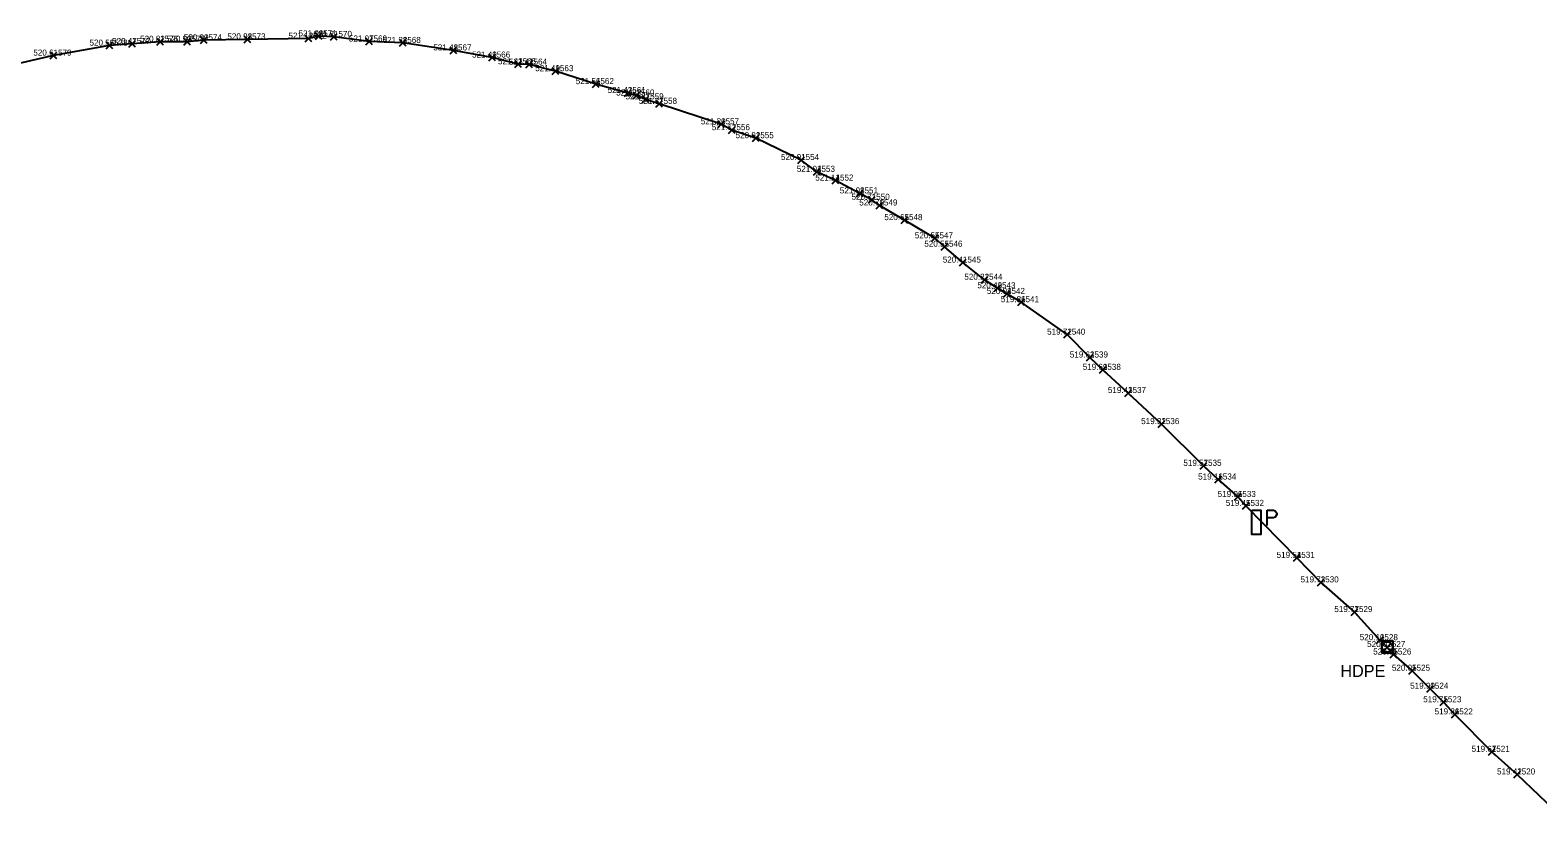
# Model space of a CAD drawing. Extents: x -874041 to -866452, y -1055592 to -1049889.
# Drawn here: x -873048.1 to -872799.1, y -1055397.3 to -1055267.6 of the extents above; entities that cross this region are included whole.
import ezdxf

# ---------------------------------------------------------------- set-up
doc = ezdxf.new("R2010")
doc.units = 0
for name, color, linetype in [('Vrstva 30', 7, 'Continuous'), ('Vrstva 32', 7, 'Continuous'), ('Vrstva 33', 7, 'Continuous'), ('Vrstva 60', 7, 'Continuous'), ('Vrstva 61', 7, 'Continuous')]:
    doc.layers.add(name, color=color, linetype=linetype)

msp = doc.modelspace()

# ---------------------------------------------------------------- linework, layer by layer
at = {"layer": 'Vrstva 30'}
msp.add_lwpolyline([(-872824.91, -1055370.41), (-872822.99, -1055370.41), (-872822.99, -1055368.49), (-872824.91, -1055368.49)], close=True, dxfattribs=at)
msp.add_circle((-872823.95, -1055369.45), 0.864, dxfattribs=at)
at = {"layer": 'Vrstva 32'}
for points in [[(-872851.86, -1055341.78), (-872854.3, -1055339.52), (-872861.27, -1055332.63), (-872866.77, -1055327.5), (-872870.93, -1055323.67), (-872873.06, -1055321.63), (-872876.81, -1055317.85), (-872884.45, -1055312.49), (-872886.77, -1055311.13), (-872888.33, -1055310.19), (-872890.48, -1055308.79), (-872894.05, -1055305.95), (-872897.09, -1055303.33), (-872898.66, -1055301.94), (-872903.7, -1055298.94), (-872907.84, -1055296.52), (-872909.11, -1055295.57), (-872911.05, -1055294.53), (-872915.1, -1055292.41), (-872918.16, -1055290.97), (-872920.77, -1055289.01), (-872928.26, -1055285.41), (-872932.2, -1055284.08), (-872934, -1055283.11), (-872944.24, -1055279.74), (-872946.45, -1055279), (-872947.98, -1055278.36), (-872949.4, -1055277.95), (-872954.67, -1055276.48), (-872961.36, -1055274.34), (-872965.71, -1055273.26), (-872967.52, -1055273.2), (-872971.8, -1055272.09), (-872978.19, -1055270.91), (-872986.57, -1055269.68), (-872992.14, -1055269.44), (-872997.94, -1055268.68), (-873000.46, -1055268.58), (-873002.13, -1055268.97), (-873012.21, -1055269.09), (-873019.41, -1055269.24), (-873022.21, -1055269.47), (-873026.63, -1055269.49), (-873031.25, -1055269.85), (-873034.99, -1055270.12), (-873044.26, -1055271.77), (-873051.62, -1055273.48)], [(-872851.86, -1055341.78), (-872848.64, -1055344.66), (-872847.29, -1055346.14), (-872838.9, -1055354.72), (-872834.95, -1055358.77), (-872829.37, -1055363.67), (-872825.17, -1055368.31), (-872823.95, -1055369.45), (-872822.94, -1055370.68), (-872819.86, -1055373.36), (-872816.84, -1055376.33), (-872814.68, -1055378.56), (-872812.8, -1055380.57), (-872806.69, -1055386.75), (-872802.49, -1055390.49), (-872795.31, -1055397.32)]]:
    msp.add_lwpolyline(points, dxfattribs=at)
at = {"layer": 'Vrstva 33'}
for points in [[(-872843.8, -1055349.35), (-872843.8, -1055346.84)], [(-872843.8, -1055346.84), (-872842.76, -1055346.84)], [(-872842.76, -1055346.84), (-872842.45, -1055346.94), (-872842.22, -1055347.35), (-872842.22, -1055347.57), (-872842.45, -1055347.99), (-872842.76, -1055348.08)], [(-872842.76, -1055348.08), (-872843.8, -1055348.08)]]:
    msp.add_lwpolyline(points, dxfattribs=at)
msp.add_lwpolyline([(-872846.34, -1055346.85), (-872844.85, -1055346.85), (-872844.85, -1055350.88), (-872846.34, -1055350.88)], close=True, dxfattribs=at)
at = {"layer": 'Vrstva 60'}
for p, q in [((-873035.54, -1055270.67), (-873034.44, -1055269.57)), ((-873034.44, -1055270.67), (-873035.54, -1055269.57)), ((-873031.8, -1055270.4), (-873030.7, -1055269.3)), ((-873030.7, -1055270.4), (-873031.8, -1055269.3)), ((-873027.18, -1055270.04), (-873026.08, -1055268.94)), ((-873026.08, -1055270.04), (-873027.18, -1055268.94)), ((-873022.76, -1055270.02), (-873021.66, -1055268.92)), ((-873021.66, -1055270.02), (-873022.76, -1055268.92)), ((-873019.96, -1055269.79), (-873018.86, -1055268.69)), ((-873018.86, -1055269.79), (-873019.96, -1055268.69)), ((-873012.76, -1055269.64), (-873011.66, -1055268.54)), ((-873011.66, -1055269.64), (-873012.76, -1055268.54)), ((-873002.68, -1055269.52), (-873001.58, -1055268.42)), ((-873001.58, -1055269.52), (-873002.68, -1055268.42)), ((-873001.01, -1055269.13), (-872999.91, -1055268.03)), ((-872999.91, -1055269.13), (-873001.01, -1055268.03)), ((-872998.49, -1055269.23), (-872997.39, -1055268.13)), ((-872997.39, -1055269.23), (-872998.49, -1055268.13)), ((-872992.69, -1055269.99), (-872991.59, -1055268.89)), ((-872991.59, -1055269.99), (-872992.69, -1055268.89)), ((-872987.12, -1055270.23), (-872986.02, -1055269.13)), ((-872986.02, -1055270.23), (-872987.12, -1055269.13)), ((-873044.81, -1055272.32), (-873043.71, -1055271.22)), ((-873043.71, -1055272.32), (-873044.81, -1055271.22)), ((-872978.74, -1055271.46), (-872977.64, -1055270.36)), ((-872977.64, -1055271.46), (-872978.74, -1055270.36)), ((-872972.35, -1055272.64), (-872971.25, -1055271.54)), ((-872971.25, -1055272.64), (-872972.35, -1055271.54)), ((-872968.07, -1055273.75), (-872966.97, -1055272.65)), ((-872966.97, -1055273.75), (-872968.07, -1055272.65)), ((-872966.26, -1055273.81), (-872965.16, -1055272.71)), ((-872965.16, -1055273.81), (-872966.26, -1055272.71)), ((-872961.91, -1055274.89), (-872960.81, -1055273.79)), ((-872960.81, -1055274.89), (-872961.91, -1055273.79)), ((-872955.22, -1055277.03), (-872954.12, -1055275.93)), ((-872954.12, -1055277.03), (-872955.22, -1055275.93)), ((-872949.95, -1055278.5), (-872948.85, -1055277.4)), ((-872948.85, -1055278.5), (-872949.95, -1055277.4)), ((-872948.53, -1055278.91), (-872947.43, -1055277.81)), ((-872947.43, -1055278.91), (-872948.53, -1055277.81)), ((-872947, -1055279.55), (-872945.9, -1055278.45)), ((-872945.9, -1055279.55), (-872947, -1055278.45)), ((-872944.79, -1055280.29), (-872943.69, -1055279.19)), ((-872943.69, -1055280.29), (-872944.79, -1055279.19)), ((-872934.55, -1055283.66), (-872933.45, -1055282.56)), ((-872933.45, -1055283.66), (-872934.55, -1055282.56)), ((-872932.75, -1055284.63), (-872931.65, -1055283.53)), ((-872931.65, -1055284.63), (-872932.75, -1055283.53)), ((-872928.81, -1055285.96), (-872927.71, -1055284.86)), ((-872927.71, -1055285.96), (-872928.81, -1055284.86)), ((-872921.32, -1055289.56), (-872920.22, -1055288.46)), ((-872920.22, -1055289.56), (-872921.32, -1055288.46)), ((-872918.71, -1055291.52), (-872917.61, -1055290.42)), ((-872917.61, -1055291.52), (-872918.71, -1055290.42)), ((-872915.65, -1055292.96), (-872914.55, -1055291.86)), ((-872914.55, -1055292.96), (-872915.65, -1055291.86)), ((-872911.6, -1055295.08), (-872910.5, -1055293.98)), ((-872910.5, -1055295.08), (-872911.6, -1055293.98)), ((-872909.66, -1055296.12), (-872908.56, -1055295.02)), ((-872908.56, -1055296.12), (-872909.66, -1055295.02)), ((-872908.39, -1055297.07), (-872907.29, -1055295.97)), ((-872907.29, -1055297.07), (-872908.39, -1055295.97)), ((-872904.25, -1055299.49), (-872903.15, -1055298.39)), ((-872903.15, -1055299.49), (-872904.25, -1055298.39)), ((-872899.21, -1055302.49), (-872898.11, -1055301.39)), ((-872898.11, -1055302.49), (-872899.21, -1055301.39)), ((-872897.64, -1055303.88), (-872896.54, -1055302.78)), ((-872896.54, -1055303.88), (-872897.64, -1055302.78)), ((-872894.6, -1055306.5), (-872893.5, -1055305.4)), ((-872893.5, -1055306.5), (-872894.6, -1055305.4)), ((-872891.03, -1055309.34), (-872889.93, -1055308.24)), ((-872889.93, -1055309.34), (-872891.03, -1055308.24)), ((-872888.88, -1055310.74), (-872887.78, -1055309.64)), ((-872887.78, -1055310.74), (-872888.88, -1055309.64)), ((-872887.32, -1055311.68), (-872886.22, -1055310.58)), ((-872886.22, -1055311.68), (-872887.32, -1055310.58)), ((-872885, -1055313.04), (-872883.9, -1055311.94)), ((-872883.9, -1055313.04), (-872885, -1055311.94)), ((-872877.36, -1055318.4), (-872876.26, -1055317.3)), ((-872876.26, -1055318.4), (-872877.36, -1055317.3)), ((-872873.61, -1055322.18), (-872872.51, -1055321.08)), ((-872872.51, -1055322.18), (-872873.61, -1055321.08)), ((-872871.48, -1055324.22), (-872870.38, -1055323.12)), ((-872870.38, -1055324.22), (-872871.48, -1055323.12)), ((-872867.32, -1055328.05), (-872866.22, -1055326.95)), ((-872866.22, -1055328.05), (-872867.32, -1055326.95)), ((-872861.82, -1055333.18), (-872860.72, -1055332.08)), ((-872860.72, -1055333.18), (-872861.82, -1055332.08)), ((-872854.85, -1055340.07), (-872853.75, -1055338.97)), ((-872853.75, -1055340.07), (-872854.85, -1055338.97)), ((-872852.41, -1055342.33), (-872851.31, -1055341.23)), ((-872851.31, -1055342.33), (-872852.41, -1055341.23)), ((-872849.19, -1055345.21), (-872848.09, -1055344.11)), ((-872848.09, -1055345.21), (-872849.19, -1055344.11)), ((-872847.84, -1055346.69), (-872846.74, -1055345.59)), ((-872846.74, -1055346.69), (-872847.84, -1055345.59)), ((-872839.45, -1055355.27), (-872838.35, -1055354.17)), ((-872838.35, -1055355.27), (-872839.45, -1055354.17)), ((-872835.5, -1055359.32), (-872834.4, -1055358.22)), ((-872834.4, -1055359.32), (-872835.5, -1055358.22)), ((-872829.92, -1055364.22), (-872828.82, -1055363.12)), ((-872828.82, -1055364.22), (-872829.92, -1055363.12)), ((-872825.72, -1055368.86), (-872824.62, -1055367.76)), ((-872824.62, -1055368.86), (-872825.72, -1055367.76)), ((-872824.5, -1055370), (-872823.4, -1055368.9)), ((-872823.4, -1055370), (-872824.5, -1055368.9)), ((-872823.49, -1055371.23), (-872822.39, -1055370.13)), ((-872822.39, -1055371.23), (-872823.49, -1055370.13)), ((-872820.41, -1055373.91), (-872819.31, -1055372.81)), ((-872819.31, -1055373.91), (-872820.41, -1055372.81)), ((-872817.39, -1055376.88), (-872816.29, -1055375.78)), ((-872816.29, -1055376.88), (-872817.39, -1055375.78)), ((-872815.23, -1055379.11), (-872814.13, -1055378.01)), ((-872814.13, -1055379.11), (-872815.23, -1055378.01)), ((-872813.35, -1055381.12), (-872812.25, -1055380.02)), ((-872812.25, -1055381.12), (-872813.35, -1055380.02)), ((-872807.24, -1055387.3), (-872806.14, -1055386.2)), ((-872806.14, -1055387.3), (-872807.24, -1055386.2)), ((-872803.04, -1055391.04), (-872801.94, -1055389.94)), ((-872801.94, -1055391.04), (-872803.04, -1055389.94))]:
    msp.add_line(p, q, dxfattribs=at)

# ---------------------------------------------------------------- texts
at = {"layer": 'Vrstva 32'}
msp.add_text('HDPE', height=2, dxfattribs=at).set_placement((-872831.7, -1055374.39))
at = {"layer": 'Vrstva 60'}
for s, p in [('1578', (-873034.99, -1055270.12)), ('1577', (-873031.25, -1055269.85)), ('1576', (-873026.63, -1055269.49)), ('1575', (-873022.21, -1055269.47)), ('1574', (-873019.41, -1055269.24)), ('1573', (-873012.21, -1055269.09)), ('1572', (-873002.13, -1055268.97)), ('1571', (-873000.46, -1055268.58)), ('1570', (-872997.94, -1055268.68)), ('1569', (-872992.14, -1055269.44)), ('1568', (-872986.57, -1055269.68)), ('1579', (-873044.26, -1055271.77)), ('1567', (-872978.19, -1055270.91)), ('1566', (-872971.8, -1055272.09)), ('1565', (-872967.52, -1055273.2)), ('1564', (-872965.71, -1055273.26)), ('1563', (-872961.36, -1055274.34)), ('1562', (-872954.67, -1055276.48)), ('1561', (-872949.4, -1055277.95)), ('1560', (-872947.98, -1055278.36)), ('1559', (-872946.45, -1055279)), ('1558', (-872944.24, -1055279.74)), ('1557', (-872934, -1055283.11)), ('1556', (-872932.2, -1055284.08)), ('1555', (-872928.26, -1055285.41)), ('1554', (-872920.77, -1055289.01)), ('1553', (-872918.16, -1055290.97)), ('1552', (-872915.1, -1055292.41)), ('1551', (-872911.05, -1055294.53)), ('1550', (-872909.11, -1055295.57)), ('1549', (-872907.84, -1055296.52)), ('1548', (-872903.7, -1055298.94)), ('1547', (-872898.66, -1055301.94)), ('1546', (-872897.09, -1055303.33)), ('1545', (-872894.05, -1055305.95)), ('1544', (-872890.48, -1055308.79)), ('1543', (-872888.33, -1055310.19)), ('1542', (-872886.77, -1055311.13)), ('1541', (-872884.45, -1055312.49)), ('1540', (-872876.81, -1055317.85)), ('1539', (-872873.06, -1055321.63)), ('1538', (-872870.93, -1055323.67)), ('1537', (-872866.77, -1055327.5)), ('1536', (-872861.27, -1055332.63)), ('1535', (-872854.3, -1055339.52)), ('1534', (-872851.86, -1055341.78)), ('1533', (-872848.64, -1055344.66)), ('1532', (-872847.29, -1055346.14)), ('1531', (-872838.9, -1055354.72)), ('1530', (-872834.95, -1055358.77)), ('1529', (-872829.37, -1055363.67)), ('1528', (-872825.17, -1055368.31)), ('1527', (-872823.95, -1055369.45)), ('1526', (-872822.94, -1055370.68)), ('1525', (-872819.86, -1055373.36)), ('1524', (-872816.84, -1055376.33)), ('1523', (-872814.68, -1055378.56)), ('1522', (-872812.8, -1055380.57)), ('1521', (-872806.69, -1055386.75)), ('1520', (-872802.49, -1055390.49))]:
    msp.add_text(s, height=1, dxfattribs=at).set_placement(p)
at = {"layer": 'Vrstva 61'}
for s, p in [('520.56 ', (-873038.32, -1055270.12)), ('520.47 ', (-873034.58, -1055269.85)), ('520.82 ', (-873029.96, -1055269.49)), ('520.90 ', (-873025.54, -1055269.47)), ('520.90 ', (-873022.74, -1055269.24)), ('520.98 ', (-873015.54, -1055269.09)), ('521.12 ', (-873005.46, -1055268.97)), ('521.08 ', (-873003.79, -1055268.58)), ('521.21 ', (-873001.27, -1055268.68)), ('521.07 ', (-872995.47, -1055269.44)), ('521.38 ', (-872989.9, -1055269.68)), ('520.61 ', (-873047.59, -1055271.77)), ('521.48 ', (-872981.52, -1055270.91)), ('521.49 ', (-872975.13, -1055272.09)), ('521.43 ', (-872970.85, -1055273.2)), ('521.41 ', (-872969.04, -1055273.26)), ('521.49 ', (-872964.69, -1055274.34)), ('521.56 ', (-872958, -1055276.48)), ('521.43 ', (-872952.73, -1055277.95)), ('521.23 ', (-872951.31, -1055278.36)), ('521.37 ', (-872949.78, -1055279)), ('521.37 ', (-872947.57, -1055279.74)), ('521.20 ', (-872937.33, -1055283.11)), ('521.12 ', (-872935.53, -1055284.08)), ('520.92 ', (-872931.59, -1055285.41)), ('520.91 ', (-872924.1, -1055289.01)), ('521.04 ', (-872921.49, -1055290.97)), ('521.14 ', (-872918.43, -1055292.41)), ('521.08 ', (-872914.38, -1055294.53)), ('520.71 ', (-872912.44, -1055295.57)), ('520.70 ', (-872911.17, -1055296.52)), ('520.65 ', (-872907.03, -1055298.94)), ('520.55 ', (-872901.99, -1055301.94)), ('520.55 ', (-872900.42, -1055303.33)), ('520.41 ', (-872897.38, -1055305.95)), ('520.22 ', (-872893.81, -1055308.79)), ('520.40 ', (-872891.66, -1055310.19)), ('520.04 ', (-872890.1, -1055311.13)), ('519.86 ', (-872887.78, -1055312.49)), ('519.72 ', (-872880.14, -1055317.85)), ('519.63 ', (-872876.39, -1055321.63)), ('519.69 ', (-872874.26, -1055323.67)), ('519.43 ', (-872870.1, -1055327.5)), ('519.32 ', (-872864.6, -1055332.63)), ('519.57 ', (-872857.63, -1055339.52)), ('519.16 ', (-872855.19, -1055341.78)), ('519.06 ', (-872851.97, -1055344.66)), ('519.45 ', (-872850.62, -1055346.14)), ('519.54 ', (-872842.23, -1055354.72)), ('519.73 ', (-872838.28, -1055358.77)), ('519.77 ', (-872832.7, -1055363.67)), ('520.10 ', (-872828.5, -1055368.31)), ('520.07 ', (-872827.28, -1055369.45)), ('520.05 ', (-872826.27, -1055370.68)), ('520.05 ', (-872823.19, -1055373.36)), ('519.90 ', (-872820.17, -1055376.33)), ('519.75 ', (-872818.01, -1055378.56)), ('519.86 ', (-872816.13, -1055380.57)), ('519.67 ', (-872810.02, -1055386.75)), ('519.42 ', (-872805.82, -1055390.49))]:
    msp.add_text(s, height=1, dxfattribs=at).set_placement(p)

doc.saveas('drawing.dxf')
